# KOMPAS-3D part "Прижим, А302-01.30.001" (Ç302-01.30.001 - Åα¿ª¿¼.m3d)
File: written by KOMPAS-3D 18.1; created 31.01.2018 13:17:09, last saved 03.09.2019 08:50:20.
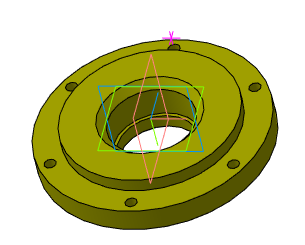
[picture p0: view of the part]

Document properties: Автор: Милов; Полное имя файла: D:\Мембранные насосы\Мембранный электропривод\А302-00.00.000 - ASTRA-302 (МЭ200)\3Д ПВХ\А302-01.30.001 - Прижим.m3d

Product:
- Part/product: Прижим  | designation А302-01.30.001
    Масса: 0.21871
    Раздел спецификации: Детали
    Форматы листов документа: A4
    source file: А302-01.30.001 - Прижим.cdw
  - Component: Прижим  | designation А302-01.30.001  | Масса: 0.22; Раздел спецификации: Детали; Форматы листов документа: A4; source file: А302-01.30.001 - Прижим.cdw
- Part/product: Прижим  | designation А302-03.30.001
    Масса: 0.218959
    Раздел спецификации: Детали
    Форматы листов документа: A4

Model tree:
1. Эскиз:1
2. Операция вращения:1
     Угол 1 = 360
3. Эскиз:5
4. Отверстие:1
     Глубина выреза = 32; Диаметр отверстия = 7; Угол конуса торца = 118; Координата Y = 60
5. Массив по концентрической сетке:1  (with: Отверстие:1, Эскиз:5)  (6 pattern instances)
     Шаг 2 = 360
6. Фаска:1
     Угол = 45; Длина 1 = 0.5; Длина 2 = 0.5
7. Фаска:2
     Угол = 45; Длина 1 = 1; Длина 2 = 1
8. Фаска:3  (with: Операция вращения:1)
     Угол = 45; Длина 1 = 5; Длина 2 = 5

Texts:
  Линейный размер с обрывом

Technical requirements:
  Gost Type A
